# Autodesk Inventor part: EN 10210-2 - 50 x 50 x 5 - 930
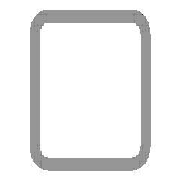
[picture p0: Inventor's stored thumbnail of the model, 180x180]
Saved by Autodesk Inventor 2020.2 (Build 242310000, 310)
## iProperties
IsCustomPart: 1
_CCFamilyMember: 16
_CCFamilyDisplayName: DIN EN 10210-2 (USAS B17.1 quadratisch) - Rohrleitung — In Klammern angegebene Größen wurden aufgehoben
_FrameMemberDoc: Frame Member File
_Version: 15.0.0
_GetPNFromCC: 1
Created: 2019-10
Part Number: EN 10210-2 - 50 x 50 x 5 - 930
Material: Stahl, weich
Description: Rohrleitung
Document SubType Name: Modeling
Standard: DIN
Designer: lutzd
Standard Revision: 2006-07
Standards Organization: DIN
Language: de-DE
Size Designation: 50 x 50 x 5
Categories: <MemberInstance><Categories><Category DisplayName="Profile" InternalName="089c4875-fa83-4c05-b084-43b9cc11f5ed" Mnemonic="GRDR"><CategoryParameter DisplayName="
Stock Number: 50 x 50 x 5
Mass: 6374.61 g
Surface Area: 3165.88 cm^2
Volume: 812.053 cm^3
Density: 7.85 g/cm^3
Appearance: Semi-Polished(8)
G_L: 930,000 mm
G_W: 50,000 mm
G_H: 50,000 mm
Dimensions: 50x50x930 mm
Mass: 6,375 kg
DocNumber: ADSK-014298
Folder: .
+7E3BE340-7D21-4DD3-92EC-7EEACB8A3671+SCHNITTDETAIL1: Schnittwinkel 90,00 grd
+69FCCCD8-F718-4049-AC98-7B276A3DBE23+SCHNITTDETAIL2: Schnittwinkel 90,00 grd
VLT_Material: Stahl, weich
Title: Profil-Bauteil
Author: lutzd
Revision Number: -
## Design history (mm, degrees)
node "Startebene"
node "Endebene"
sketch "Skizze"
  geometry: L1 (-25, -17.5)-(-25, 17.5); L2 (-17.5, 25)-(17.5, 25); L3 (25, 17.5)-(25, -17.5); L4 (17.5, -25)-(-17.5, -25); L5 (-15, 20)-(15, 20); L6 (20, 15)-(20, -15); L7 (15, -20)-(-15, -20); L8 (-20, -15)-(-20, 15); L9 (0, 37.175)-(0, -37.175) reference; L10 (-37.175, 0)-(37.175, 0) reference; A1 r 7.5 centre (-17.5, -17.5) between (-25, -17.5) and (-17.5, -25); A2 r 7.5 centre (-17.5, 17.5) between (-17.5, 25) and (-25, 17.5); A3 r 7.5 centre (17.5, 17.5) between (25, 17.5) and (17.5, 25); A4 r 7.5 centre (17.5, -17.5) between (17.5, -25) and (25, -17.5); A5 r 5 centre (-15, -15) between (-20, -15) and (-15, -20); A6 r 5 centre (-15, 15) between (-15, 20) and (-20, 15); A7 r 5 centre (15, 15) between (20, 15) and (15, 20); A8 r 5 centre (15, -15) between (15, -20) and (20, -15)
  constraints: 16 end point, 16 point on circle, 16 tangent, 8 centre point, 6 equal radius, 4 parallel, 2 perpendicular, 2 other
  dimensions: "d7" = 7.5 radius of A1 (= G_IR); "d10" = 50 distance between parallel lines of L2 L4 (= G_H); "d11" = 50 distance between parallel lines of L1 L3 (= G_W); "d12" = 5 distance between parallel lines of L3 L6 (= G_T); "d15" = 25 distance between parallel lines of L2 L10 (= 0.5 x d10); "d16" = 25 distance between parallel lines of L9 L3 (= 0.5 x d11); "d19" = 5 radius of A5 (= G_T); "d20" = 5 distance between parallel lines of L4 L7 (= G_T)
extrude "Körper" new body sketch "Skizze" stored distance "d3" = 930 (= G_L); taper "d4" = 0 deg
node "Driven Length"
  sketch "Sketch3"
    geometry: L1 (0, 0)-(10, 0) reference
    constraints: 2 end point, 1 horizontal
  workplane "Work Plane3"
  sketch "Sketch4"
    geometry: L1 (-2, 50)-(12, 50) reference; L2 (-2, 980)-(12, 980) reference
    dimensions: "d18" = 930 distance between parallel lines of L1 L2 (derived)
workplane "Arbeitsebene4"
feature "Trennen1"
workplane "Arbeitsebene5"
feature "Trennen2"
body "Solid1"
other parameters: "G_W" = 50 [user parameter; used in 1 equation term], "G_H" = 50 [user parameter; used in 1 equation term], "G_T" = 5 [user parameter; used in 3 equation terms], "G_IR" = 7.5 [user parameter; used in 1 equation term], "G_L" = 930 (= d18) [user parameter; used in 1 equation term], "d17" = 90 deg
